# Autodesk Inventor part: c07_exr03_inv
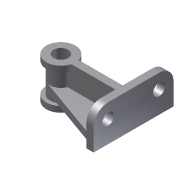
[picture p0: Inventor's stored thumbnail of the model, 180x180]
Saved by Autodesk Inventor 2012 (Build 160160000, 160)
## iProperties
Shininess: 77.0
Length Units: 11269
Angle Units: 11279
Time Units: 11290
Mass Units: 11283
Length Display Precision: 3
Angle Display Precision: 2
Created: 2001-12
Part Number: c07_exr03_inv
Document SubType Name: Modeling
Density: 1 g/cm^3
Material: Default
Density: 0.0
Volumn: 0.0
Area: 0.0
PropertySet Name: Model Information
Control State: 0
Master: False
Checked Out: False
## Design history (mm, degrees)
sketch "Sketch1"
  geometry: L1 (67.049, 55)-(67.049, -55); L2 (60.402, -45.579)-(-27.979, -14.132); L3 (-27.979, 14.132)-(60.402, 45.579); A1 r 10 centre (57.049, -55) between (67.049, -55) and (60.402, -45.579); A2 r 15 centre (-22.951, 0) between (-27.979, 14.132) and (-27.979, -14.132); A3 r 10 centre (57.049, 55) between (60.402, 45.579) and (67.049, 55)
  constraints: 6 end point, 6 point on circle, 6 tangent, 3 centre point, 1 equal length, 1 equal radius, 1 vertical
  dimensions: "d0" = 15 radius of A2; "d1" = 10 radius of A1; "d2" = 90 distance from line of L1 A2.centre; "d3" = 110 distance of L1.start L1.end
extrude "Extrusion1" new body sketch "Sketch1" distance "d4" = 10; taper "d5" = 0 deg
sketch "Sketch2"
  geometry: L1 (0, 110)-(0, 0) reference; L2 (0, 0)-(-30, 0); L3 (-50, 20)-(-50, 90); L4 (-30, 110)-(0, 110); C1 r 8 at (-30, 90); C2 r 8 at (-30, 20); A1 r 20 centre (-30, 20) between (-50, 20) and (-30, 0); A2 r 20 centre (-30, 90) between (-30, 110) and (-50, 90)
  constraints: 6 end point, 4 centre point, 4 point on circle, 4 tangent, 3 perpendicular, 2 coincident, 1 equal radius, 1 parallel
  dimensions: "d6" = 20 radius of A2; "d7" = 50 distance between parallel lines of L1 L3; "d10" = 16 diameter of C1
extrude "Extrusion2" join sketch "Sketch2" distance "d8" = 10; taper "d9" = 0 deg
workplane "Work Plane1"
sketch "Sketch3"
  geometry: C1 r 15 at (-22.951, 0); A1 r 15 centre (-22.951, 0) between (-27.979, 14.132) and (-27.979, -14.132) reference
  constraints: 2 concentric, 1 centre point
extrude "Extrusion3" join sketch "Sketch3" distance "d12" = 56; taper "d13" = 0 deg
sketch "Sketch4"
  geometry: L1 (7.951, 40)-(-57.058, 40); L2 (7.951, 40)-(37.951, 40) reference; L3 (-67.049, 50)-(-67.049, 30) reference; L4 (-77.049, 0)-(-77.049, 30) reference; L5 (-67.049, 0)-(-77.049, 0) reference; A1 r 10 centre (-57.058, 50) between (-67.049, 49.599) and (-57.058, 40)
  constraints: 2 end point, 2 point on circle, 2 point on line, 1 centre point, 1 horizontal, 1 tangent
  dimensions: "d14" = 85 distance from line of L4 L1.start; "d15" = 50 distance from line of L5 A1.centre
feature "Rib1" sketch "Sketch4" dims "d16" = 1, "d17" = 10
sketch "Sketch5"
  geometry: C1 r 20 at (-22.951, 0); 1 further point
  constraints: 1 centre point, 1 coincident
  dimensions: "d18" = 40 diameter of C1
extrude "Extrusion4" join sketch "Sketch5" distance "d19" = 8; taper "d20" = 0 deg
workplane "Work Plane2"
mirror "Mirror1"
sketch "Sketch6"
  geometry: A1 r 20 centre (-22.951, 0) between (-3.586, 5) and (-3.586, -5) reference
hole "Hole1" sketch "Sketch6" at (-22.951, 0) diameter "d22" = 20; stored, may be unused: countersink angle "d26" = 82 deg, drill point angle "d28" = 118 deg; dims "d23" = 6, "d24" = 4, "d25" = 2, "d27" = 8
body "Solid1"
other parameters: "d21" = -28
